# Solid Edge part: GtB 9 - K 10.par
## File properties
Author: Carsten
Template: Normal.par
Last saved by: Carsten
Revision: 2
Application: Solid Edge
Genauigkeit: 0,99
Teilflächenrmatvorlage: Model Default
Coef. of Thermal Exp: 0.0
Thermal Conductivity: 0.0
Specific Heat: 0.0
Modulus of Elasticity: 0.0
Poission's Ratio: 0.0
Yield Stress: 0.0
Ultimate Stress: 0.0
Elongation: 0.0
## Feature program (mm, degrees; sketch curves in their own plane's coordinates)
sketch for "unnamed Protrusion 1" plane through (0, 0, 0) normal (0, 0, 1) x-axis (1, 0, 0)
  line (-29.5468, 37.9488) -> (50.4532, 37.9488)
  line (50.4532, 37.9488) -> (50.4532, -42.0512)
  line (50.4532, -42.0512) -> (-29.5468, -42.0512)
  line (-29.5468, -42.0512) -> (-29.5468, 37.9488)
extrude "unnamed Protrusion 1" add finite 10 along +normal
sketch for "Ausprägung_2" #1 plane through (10.4532, -2.0512, 10) normal (0, 0, 1) x-axis (0, 1, 0)
  line (15, 30) -> (15, 15)
  line (15, 15) -> (30, 15)
  line (30, 15) -> (30, 30)
  line (30, 30) -> (15, 30)
sketch for "Ausprägung_2" #2 plane through (10.4532, -2.0512, 10) normal (0, 0, 1) x-axis (0, 1, 0)
  line (-30, -15) -> (-30, -30)
  line (-30, -30) -> (-15, -30)
  line (-15, -30) -> (-15, -15)
  line (-15, -15) -> (-30, -15)
sketch for "Ausprägung_2" #3 plane through (10.4532, -2.0512, 10) normal (0, 0, 1) x-axis (0, 1, 0)
  line (15, -30) -> (15, -15)
  line (15, -15) -> (30, -15)
  line (30, -15) -> (30, -30)
  line (30, -30) -> (15, -30)
sketch for "Ausprägung_2" #4 plane through (10.4532, -2.0512, 10) normal (0, 0, 1) x-axis (0, 1, 0)
  line (-30, 30) -> (-15, 30)
  line (-15, 30) -> (-15, 15)
  line (-15, 15) -> (-30, 15)
  line (-30, 15) -> (-30, 30)
  dimension (linear) = 15
  dimension (linear) = 15
  dimension (linear) = 15
  dimension (linear) = 15
  dimension (linear) = 15
  dimension (linear) = 30
  dimension (linear) = 15
  dimension (linear) = 15
extrude "Ausprägung_2" add finite 45 along +normal
sketch for "Ausprägung_3" plane through (10.4532, -2.0512, 10) normal (0, 0, 1) x-axis (0, 1, 0)
  line (-40, 5) -> (40, 5)
  line (40, 5) -> (40, -5)
  line (40, -5) -> (-40, -5)
  line (-40, -5) -> (-40, 5)
  dimension (linear) = 40
  dimension (linear) = 40
  dimension (linear) = 40
extrude "Ausprägung_3" add finite 75 along +normal
sketch for "Ausschnitt_1" plane through (15.4532, -2.0512, 47.5) normal (1, 0, 0) x-axis (0, 1, 0)
  line (-25, 37.5) -> (0, -7.5)
  line (0, -7.5) -> (25, 37.5)
  line (25, 37.5) -> (-25, 37.5)
extrude "Ausschnitt_1" cut finite 31.75 along -normal
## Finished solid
Body 1: solid body, 33 faces, 81 edges, 54 vertices.
  Faces by surface: plane 33
  Edges by curve: line 81
Bounding box of the edges (mm): 80.000 x 80.000 x 85.000, from (-29.5468, -42.0512, 0) to (50.4532, 37.9488, 85).
Planar faces by outward normal: +x 6, +y 5, +z 8, -x 6, -y 5, -z 1, oblique 2
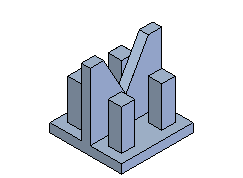
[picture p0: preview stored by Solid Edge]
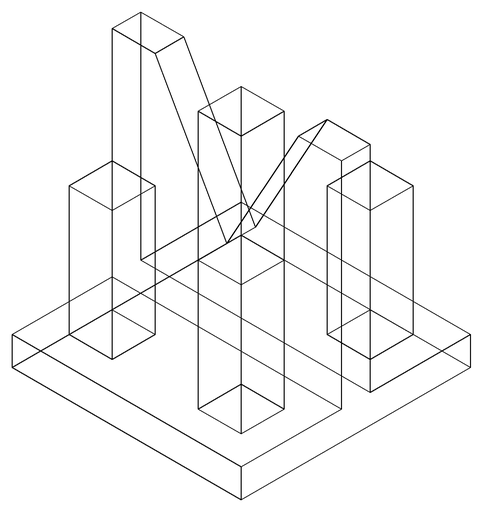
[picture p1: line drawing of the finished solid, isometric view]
